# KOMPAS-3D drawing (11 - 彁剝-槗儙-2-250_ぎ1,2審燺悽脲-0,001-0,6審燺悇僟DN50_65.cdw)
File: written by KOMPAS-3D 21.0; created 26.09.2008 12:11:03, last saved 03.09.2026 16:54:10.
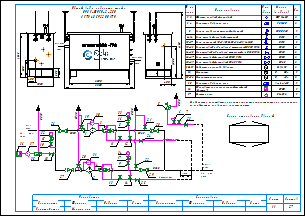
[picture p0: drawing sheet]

Sheets 1-2: A3, landscape

Document properties: Наименование: Макро:21; Автор: RaskoAdmin; Форматы листов документа: 2xA3; Полное имя файла: \\UR38nt01\Departments\КТО\КБ ПУРДГ\Заявки\Прайс-лист на типовые шкафы ГРПШ\ПРДГ_стандарт_20_03_2026\ПРДГ с РДГ(Н, В)\ПРДГ-ШУГО-2-250_до1,2МПа_Рвых-0,001-0,6МПа_РДГ_DN50_65.cdw

Title block, sheet 1: Наименование: Пункт учета газа / ПУГ-Ш-400-Р / ЛГТИ.485922.001ТУ; designation: ЛГТИ.03.4411141; sheet number: 1; Количество листов документа: 2; organisation: ООО "ЭЛЬСТЕР Газэлектроника"; Форматы листов документа: A3; stored path: C:\Рабочие документы\Компас\ПУГ\Схема.cdw; Разработал: Устинов; Проверил: Кошкин; Утвердил: Кошкин
Title block, sheet 2: sheet number: 2; stored path: D:\Рабочие документы\Заявки\ПУРДГ\ПУРДГ-ШУЭО-2-100-Р 4411220.cdw; designation, second copy: ЛГТИ.03.4411141-

Views: Вид 1, Вид 2
Referenced files: wcvoit.frw
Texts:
  Normal
  Общий вид и габариты шкафа
  ПРДГ-ШУГО-2-250
  DN65
  Выход газа
  DN50
  Вход газа
  logo-rasko-ge.png
  Вход
  газа
  PDI
  Выход
  Р=     кПа
  DN20
  Импульс DN20
  ≥5DN
  HYSWLongFangSong
  Р=       МПа
  № на
  схеме
  Усл.
  обозн.
  Марка
  (модель)
  Кол.
  Фильтр газовый фланцевый
  ФГ 16-50
  Регулятор давления газа
  РДГ-50
  Клапан предохранительный сбросной
  КПС DN20
  Кран шаровой газовый латунный
  DN15
  Кран кнопочный VE-РАСКО-НЗ-1,6-G1/2-М20
  Кран шаровой "под приварку" штуцерный DN20 PN16
  Кран шаровой "под приварку" штуцерный п/п DN20 PN16
  Кран шаровой фланцевый DN50 PN16
  Кран шаровой фланцевый DN65 PN16
  Индикатор перепада давления
  Delta 15
  Манометр
  Манометр-напоромер
  0...     МПа
  0...     кПа
  Обогреватель газогорелочный шкафной
  (Эльтон")
  Счетчик газа
  Venio-A-15
  ОГШН
  BK-G1,6
  Схема открывания дверей
  Предприятие изготовитель может заменять комплектующие на аналогичные,
  не ухудшающие заявленных характеристик.
  Должность
  Конструктор
  Фамилия
  Подпись
  Дата
  Согласовано
  Максимкин
  Лист
  Листов
  POLYLINE_STYLE_0.18_RGB_0_0_0
  POLYLINE_STYLE_0.50_RGB_0_0_0
  POLYLINE_STYLE_0.34_RGB_0_0_0
  PHANTOM_RGB_0_0_0_SC_1_THICK_0.18
  K5LT_THIN_RGB_0_0_0_THICK_0.18
  K5LT32769_RGB_0_0_0_THICK_0.18
  K5LT12_RGB_0_0_0_SC_1_THICK_0.18
  K5LT_DASHED_RGB_0_0_0_SC_1_THICK_0.18
  ACISOTGL_RGB_0_0_0_SC_0.8_THICK_0.25
  CONTINUOUS_RGB_0_127_31_THICK_0.3
  CONTINUOUS_RGB_0_0_255_THICK_0.35
  CONTINUOUS_RGB_255_0_0_THICK_0.35
  POLYLINE_STYLE_0.25_RGB_0_0_0
  CONTINUOUS_RGB_0_0_0_THICK_0.5
  POLYLINE_STYLE_0.35_RGB_0_0_255
  CONTINUOUS_RGB_0_0_0_THICK_0.4
  CONTINUOUS_RGB_0_0_0_THICK_0.35
  Без оформления
Dimensions and other numbers on the sheet: 1; 400; 1050; 500; 305; 1565; 2800; 1000; 4130; 2500; 2; 3; 4; 5; 10; 27; 28; 29; 23; 8; 12; 19; 20; 21; 22; 25; 24; 30; 31; 15; 16; 32; 26; 6; 7; 11; 14; 13; 33; 9; 17; 34; 18; 35; 36; 37; 1, 2; 3, 4; 6-14; 15-17; 18-23; 24-25; 26-27; 28-29; 30-31; 33-34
